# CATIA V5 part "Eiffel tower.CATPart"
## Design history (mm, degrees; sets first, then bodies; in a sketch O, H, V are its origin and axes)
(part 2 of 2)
    symmetry: P8 P14 V, P7 P15 V, L8 L13 V, P11 P16 V, L11 L14 V, P12 P17 V, L12 L15 V, P1 P18 V, L10 L16 V, P4 P19 V, P10 P20 V, L9 L17 V, P6 P21 V, L6 L18 V, P9 P22 V, P5 P23 V, L7 L19 V, P3 P24 V, L2 L20 V, P2 P25 V, L1 L21 V, L4 L22 V, L5 L23 V, L3 L24 V
  Pocket15: profile Sketch37, direction (0, 0.8737, -0.4864), length 0.5
  Sketch38 on face of CloseSurface2, origin (0, -38.813, 21.6056), H (1, 0, 0), V (0, 0.4864, 0.8737)
    line L1 (-40.0899, -6.8005) -> (-28.2213, -6.8005)
    point P1 (-40.0899, -6.8005)
    point P2 (-28.2213, -6.8005)
    reference projected point E1 (-28.2213, -6.8005) from vertex [face of Pocket15 from Sketch37.L7 | face of Pocket8 from Sketch30.L6 | face of CloseSurface2]
    reference projected line E2 (-25.8693, 22.4371) -> (-28.4506, 17.13) from edge [face of CloseSurface2 | face of Pocket12 from Sketch34.L5]
    line L2 (-28.2213, -6.8005) -> (-27.7989, -5.8005)
    reference projected line E4 (-15.8722, 22.4371) -> (-32.8928, -17.8606) from edge [face of CloseSurface2 | face of Pocket8 from Sketch30.L6]
    line L3 (-27.7989, -5.8005) -> (-39.6675, -5.8005)
    point P3 (-27.7989, -5.8005)
    line L4 (-40.0899, -6.8005) -> (-39.6675, -5.8005)
    point P4 (-39.6675, -5.8005)
    point P5 (39.6675, -5.8005)
    point P6 (27.7989, -5.8005)
    line L5 (27.7989, -5.8005) -> (39.6675, -5.8005)
    point P7 (28.2213, -6.8005)
    point P8 (40.0899, -6.8005)
    line L6 (40.0899, -6.8005) -> (28.2213, -6.8005)
    point P9 (27.7989, -5.8005)
    point P10 (28.2213, -6.8005)
    line L7 (28.2213, -6.8005) -> (27.7989, -5.8005)
    point P11 (39.6675, -5.8005)
    point P12 (40.0899, -6.8005)
    line L8 (40.0899, -6.8005) -> (39.6675, -5.8005)
    horizontal: L1 H, L3 H
    coincidence: P2 E1, P1 E2, P5 P11, P6 P9, P7 P10, P8 P12
    parallelism: L2 E4, L4 L2
    symmetry: P4 P5 V, P3 P6 V, L3 L5 V, P2 P7 V, P1 P8 V, L1 L6 V, P3 P9 V, P2 P10 V, L2 L7 V, P4 P11 V, P1 P12 V, L4 L8 V
  Pocket16: profile Sketch38, direction (0, 0.8737, -0.4864), length 0.5
  Sketch39 on face of CloseSurface2, origin (0, -38.813, 21.6056), H (1, 0, 0), V (0, 0.4864, 0.8737)
    line L1 (-39.6035, -5.8005) -> (-31.5781, -1.5166)
    point P1 (-39.6035, -5.8005)
    point P2 (-24.3628, 2.335)
    reference projected line E1 (-35.6047, -11.8753) -> (-28.8395, -8.264) from edge [face of CloseSurface2 | face of Pocket15 from Sketch37.L6]
    reference projected point E2 (-39.6035, -5.8005) from vertex [face of Pocket16 from Sketch38.L3 | face of Pocket12 from Sketch34.L5 | face of CloseSurface2]
    reference projected line E3 (-15.8722, 22.4371) -> (-32.8928, -17.8606) from edge [face of CloseSurface2 | face of Pocket8 from Sketch30.L6]
    line L2 (-38.8589, -4.2694) -> (-32.258, -0.7459)
    point P3 (-38.8589, -4.2694)
    point P4 (-23.7446, 3.7985)
    reference projected line E4 (-25.8693, 22.4371) -> (-28.4506, 17.13) from edge [face of CloseSurface2 | face of Pocket12 from Sketch34.L5]
    reference projected line E6 (-15.8722, 22.4371) -> (-32.8928, -17.8606) from edge [face of CloseSurface2 | face of Pocket8 from Sketch30.L6]
    line L3 (-24.3628, 2.335) -> (-23.7446, 3.7985)
    line L4 (-39.6035, -5.8005) -> (-38.8589, -4.2694)
    point P5 (-34.9348, 3.7985)
    line L5 (-34.9348, 3.7985) -> (-31.3523, -0.2625)
    line L6 (-27.7989, -5.8005) -> (-31.5781, -1.5166)
    point P6 (-27.7989, -5.8005)
    reference projected point E7 (-27.7989, -5.8005) from vertex [face of Pocket16 from Sketch38.L3 | face of Pocket8 from Sketch30.L6 | face of CloseSurface2]
    line L7 (-34.9348, 3.7985) -> (-35.4082, 2.8251)
    point P7 (-35.4082, 2.8251)
    point P8 (-31.5781, -1.5166)
    line L8 (-30.6724, -1.0331) -> (-24.3628, 2.335)
    point P9 (-30.6724, -1.0331)
    point P10 (-32.258, -0.7459)
    line L9 (-31.3523, -0.2625) -> (-23.7446, 3.7985)
    point P11 (-31.3523, -0.2625)
    line L10 (-30.6724, -1.0331) -> (-27.3676, -4.7793)
    line L11 (-32.258, -0.7459) -> (-35.4082, 2.8251)
    line L12 (-27.7989, -5.8005) -> (-27.3676, -4.7793)
    point P12 (-27.3676, -4.7793)
    point P13 (31.5781, -1.5166)
    point P14 (39.6035, -5.8005)
    line L13 (39.6035, -5.8005) -> (31.5781, -1.5166)
    point P15 (32.258, -0.7459)
    point P16 (38.8589, -4.2694)
    line L14 (38.8589, -4.2694) -> (32.258, -0.7459)
    point P17 (35.4082, 2.8251)
    line L15 (32.258, -0.7459) -> (35.4082, 2.8251)
    point P18 (31.3523, -0.2625)
    point P19 (34.9348, 3.7985)
    line L16 (34.9348, 3.7985) -> (31.3523, -0.2625)
    point P20 (23.7446, 3.7985)
    line L17 (31.3523, -0.2625) -> (23.7446, 3.7985)
    point P21 (24.3628, 2.335)
    point P22 (30.6724, -1.0331)
    line L18 (30.6724, -1.0331) -> (24.3628, 2.335)
    point P23 (27.3676, -4.7793)
    line L19 (30.6724, -1.0331) -> (27.3676, -4.7793)
    point P24 (27.7989, -5.8005)
    line L20 (27.7989, -5.8005) -> (31.5781, -1.5166)
    line L21 (34.9348, 3.7985) -> (35.4082, 2.8251)
    line L22 (24.3628, 2.335) -> (23.7446, 3.7985)
    line L23 (27.7989, -5.8005) -> (27.3676, -4.7793)
    line L24 (39.6035, -5.8005) -> (38.8589, -4.2694)
    parallelism: L1 E1, L6 L5, L7 L4, L12 L3
    coincidence: P1 E2, P2 E3, P3 E4, P4 E6, P5 L4, P6 E7, L5 P9, L1 L8, L6 P10, L2 L9, L5 L10, L6 L11
    fix: L5
    symmetry: P8 P13 V, P1 P14 V, L1 L13 V, P10 P15 V, P3 P16 V, L2 L14 V, P7 P17 V, L11 L15 V, P11 P18 V, P5 P19 V, L5 L16 V, P4 P20 V, L9 L17 V, P2 P21 V, P9 P22 V, L8 L18 V, P12 P23 V, L10 L19 V, P6 P24 V, L6 L20 V, L7 L21 V, L3 L22 V, L12 L23 V, L4 L24 V
  Pocket17: profile Sketch39, direction (0, 0.8737, -0.4864), length 0.5
  Sketch40 on face of CloseSurface2, origin (0, -38.813, 21.6056), H (1, 0, 0), V (0, 0.4864, 0.8737)
    line L1 (-34.9348, 3.7985) -> (-23.7446, 3.7985)
    point P1 (-34.9348, 3.7985)
    point P2 (-23.7446, 3.7985)
    reference projected point E1 (-34.9348, 3.7985) from vertex [face of Pocket17 from Sketch39.L5 | face of Pocket12 from Sketch34.L5 | face of CloseSurface2]
    reference projected line E2 (-15.8722, 22.4371) -> (-32.8928, -17.8606) from edge [face of CloseSurface2 | face of Pocket8 from Sketch30.L6]
    line L2 (-34.4484, 4.7985) -> (-23.3222, 4.7985)
    point P3 (-23.3222, 4.7985)
    point P4 (-34.4484, 4.7985)
    line L3 (-23.3222, 4.7985) -> (-26.878, 8.8292)
    reference projected line E3 (-31.3523, -0.2625) -> (-34.9348, 3.7985) from edge [face of CloseSurface2 | face of Pocket17 from Sketch39.L5]
    point P5 (-30.4942, 12.9283)
    line L4 (-22.8905, 5.8207) -> (-25.9707, 9.3123)
    point P6 (-22.8905, 5.8207)
    point P7 (-30.0203, 13.9027)
    point P8 (-19.4769, 13.9027)
    line L5 (-19.4769, 13.9027) -> (-26.6507, 10.0831)
    point P9 (-33.7048, 6.3273)
    line L6 (-20.0942, 12.4411) -> (-25.9707, 9.3123)
    point P10 (-20.0942, 12.4411)
    point P11 (-25.9707, 9.3123)
    line L7 (-26.6507, 10.0831) -> (-30.0203, 13.9027)
    point P12 (-26.6507, 10.0831)
    point P13 (-26.878, 8.8292)
    line L8 (-27.5581, 9.6) -> (-30.4942, 12.9283)
    point P14 (-27.5581, 9.6)
    line L9 (-26.878, 8.8292) -> (-34.4484, 4.7985)
    line L10 (-27.5581, 9.6) -> (-33.7048, 6.3273)
    line L11 (-20.0942, 12.4411) -> (-19.4769, 13.9027)
    line L12 (-30.4942, 12.9283) -> (-30.0203, 13.9027)
    line L13 (-23.7446, 3.7985) -> (-23.3222, 3.7985)
    point P15 (-23.3222, 3.7985)
    line L14 (-23.3222, 3.7985) -> (-22.6049, 5.4969)
    point P16 (-22.6049, 5.4969)
    line L15 (-22.6049, 5.4969) -> (-22.8905, 5.8207)
    line L16 (-34.9348, 3.7985) -> (-35.3834, 3.7985)
    point P17 (-35.3834, 3.7985)
    line L17 (-35.3834, 3.7985) -> (-34.3102, 6.005)
    point P18 (-34.3102, 6.005)
    line L18 (-34.3102, 6.005) -> (-33.7048, 6.3273)
    construction line L19 through (0, 7.597) direction (0, -1)
    point P21 (23.3222, 4.7985)
    point P22 (34.4484, 4.7985)
    line L20 (34.4484, 4.7985) -> (23.3222, 4.7985)
    point P23 (26.878, 8.8292)
    line L21 (26.878, 8.8292) -> (34.4484, 4.7985)
    point P24 (33.7048, 6.3273)
    point P25 (27.5581, 9.6)
    line L22 (27.5581, 9.6) -> (33.7048, 6.3273)
    point P26 (30.4942, 12.9283)
    line L23 (27.5581, 9.6) -> (30.4942, 12.9283)
    point P27 (30.0203, 13.9027)
    point P28 (26.6507, 10.0831)
    line L24 (26.6507, 10.0831) -> (30.0203, 13.9027)
    point P29 (19.4769, 13.9027)
    line L25 (19.4769, 13.9027) -> (26.6507, 10.0831)
    point P30 (25.9707, 9.3123)
    point P31 (20.0942, 12.4411)
    line L26 (20.0942, 12.4411) -> (25.9707, 9.3123)
    point P32 (22.8905, 5.8207)
    line L27 (22.8905, 5.8207) -> (25.9707, 9.3123)
    line L28 (23.3222, 4.7985) -> (26.878, 8.8292)
    point P33 (22.6049, 5.4969)
    point P34 (23.3222, 3.7985)
    line L29 (23.3222, 3.7985) -> (22.6049, 5.4969)
    line L30 (22.6049, 5.4969) -> (22.8905, 5.8207)
    point P35 (23.7446, 3.7985)
    point P36 (34.9348, 3.7985)
    line L31 (34.9348, 3.7985) -> (23.7446, 3.7985)
    line L32 (23.7446, 3.7985) -> (23.3222, 3.7985)
    point P37 (35.3834, 3.7985)
    line L33 (34.9348, 3.7985) -> (35.3834, 3.7985)
    point P38 (34.3102, 6.005)
    line L34 (35.3834, 3.7985) -> (34.3102, 6.005)
    line L35 (34.3102, 6.005) -> (33.7048, 6.3273)
    line L36 (30.4942, 12.9283) -> (30.0203, 13.9027)
    line L37 (20.0942, 12.4411) -> (19.4769, 13.9027)
    distance L3 L4 = 1
    distance L6 L5 = 1
    horizontal: L1 H, L2 H, L13 H, L16 H
    coincidence: P1 E1, P2 E2, L4 L7, L6 P13, L5 P14, L3 L8, L6 L9, L5 L10, P16 L4, P18 L5
    parallelism: L3 E3, L15 L3, L17 L12, L18 L5
    symmetry: V L19 L1, P3 P21 L19, P4 P22 L19, L2 L20 L19, P13 P23 L19, L9 L21 L19, P9 P24 L19, P14 P25 L19, L10 L22 L19, P5 P26 L19, L8 L23 L19, P7 P27 L19, P12 P28 L19, L7 L24 L19, P8 P29 L19, L5 L25 L19, P11 P30 L19, P10 P31 L19, L6 L26 L19, P6 P32 L19, L4 L27 L19, L3 L28 L19, P16 P33 L19, P15 P34 L19, L14 L29 L19, L15 L30 L19, P2 P35 L19, P1 P36 L19, L1 L31 L19, L13 L32 L19, P17 P37 L19, L16 L33 L19, P18 P38 L19, L17 L34 L19, L18 L35 L19, L12 L36 L19, L11 L37 L19
  Pocket18: profile Sketch40, direction (0, 0.8737, -0.4864), length 0.5
  Sketch41 on face of CloseSurface2, origin (0, -38.813, 21.6056), H (1, 0, 0), V (0, 0.4864, 0.8737)
    line L1 (-30.0203, 13.9027) -> (-19.4769, 13.9027)
    point P1 (-30.0203, 13.9027)
    point P2 (-19.4769, 13.9027)
    reference projected line E1 (-25.8693, 22.4371) -> (-28.4506, 17.13) from edge [face of CloseSurface2 | face of Pocket12 from Sketch34.L5]
    reference projected point E3 (-30.0203, 13.9027) from vertex [face of Pocket18 from Sketch40.L7 | face of Pocket12 from Sketch34.L5 | face of CloseSurface2]
    reference projected line E4 (-15.8722, 22.4371) -> (-32.8928, -17.8606) from edge [face of CloseSurface2 | face of Pocket8 from Sketch30.L6]
    line L2 (-29.5339, 14.9027) -> (-19.0545, 14.9027)
    point P3 (-29.5339, 14.9027)
    reference projected line E5 (-25.8693, 22.4371) -> (-28.4506, 17.13) from edge [face of CloseSurface2 | face of Pocket12 from Sketch34.L5]
    line L3 (-30.0203, 13.9027) -> (-29.5339, 14.9027)
    line L4 (-19.4769, 13.9027) -> (-19.0545, 14.9027)
    reference projected line E7 (-15.8722, 22.4371) -> (-32.8928, -17.8606) from edge [face of CloseSurface2 | face of Pocket8 from Sketch30.L6]
    point P4 (-19.0545, 14.9027)
    point P5 (29.5339, 14.9027)
    point P6 (30.0203, 13.9027)
    line L5 (30.0203, 13.9027) -> (29.5339, 14.9027)
    point P7 (19.0545, 14.9027)
    line L6 (29.5339, 14.9027) -> (19.0545, 14.9027)
    point P8 (19.4769, 13.9027)
    line L7 (30.0203, 13.9027) -> (19.4769, 13.9027)
    line L8 (19.4769, 13.9027) -> (19.0545, 14.9027)
    distance L1 L2 = 1
    horizontal: L1 H, L2 H
    coincidence: P1 E1, P1 E3, P2 E4, P3 E5
    parallelism: L4 E7
    symmetry: P3 P5 V, P1 P6 V, L3 L5 V, P4 P7 V, L2 L6 V, P2 P8 V, L1 L7 V, L4 L8 V
  Pocket19: profile Sketch41, direction (0, 0.8737, -0.4864), length 0.5
  CircPattern17: of Pocket19, instances 4, angular step 90, axis from edge [ZX plane of AxisSystem1 | YZ plane of AxisSystem1]
  CircPattern18: of Pocket18, instances 4, angular step 90, axis from edge [ZX plane of AxisSystem1 | YZ plane of AxisSystem1]
  CircPattern19: of Pocket16, instances 4, angular step 90, axis from edge [ZX plane of AxisSystem1 | YZ plane of AxisSystem1]
  CircPattern20: of Pocket17, instances 4, angular step 90, axis from edge [ZX plane of AxisSystem1 | YZ plane of AxisSystem1]
  CircPattern21: of Pocket15, instances 4, angular step 90, axis from edge [ZX plane of AxisSystem1 | YZ plane of AxisSystem1]
  Sketch42 on face of CloseSurface2, origin (0, -38.813, 21.6056), H (1, 0, 0), V (0, 0.4864, 0.8737)
    arc A1 centre (0, -15.7693) radius 30 from (17.6145, 8.5151) to (16.7953, 9.0886) ccw
    reference projected arc E1 centre (0, -15.7693) radius 30 from (22.7492, 3.7877) to (-22.7492, 3.7877) ccw from edge [face of CloseSurface2 | face of Pocket9 from Sketch31.A1]
    line L1 (17.6145, 8.5151) -> (19.9099, 11.7932)
    line L2 (-17.6145, 8.5151) -> (-19.9969, 11.9175)
    line L3 (-19.9969, 11.9175) -> (-19.5008, 12.9525)
    line L4 (-17.6271, 16.3175) -> (-16.7442, 16.787)
    line L5 (-12.9374, 16.5386) -> (-11.8663, 16.5386)
    line L6 (16.7034, 16.7103) -> (17.7666, 16.5797)
    line L7 (19.4776, 12.9193) -> (19.9099, 11.7932)
    point P7 (12.9374, 16.5386)
    point P8 (11.8663, 16.5386)
    point P9 (8.5706, 16.5386)
    point P10 (7.54, 16.5386)
    point P11 (4.4707, 16.5386)
    point P12 (3.4632, 16.5386)
    point P13 (0.5, 16.5386)
    point P14 (-0.5, 16.5386)
    point P15 (-3.4632, 16.5386)
    point P16 (-4.4707, 16.5386)
    point P17 (-7.54, 16.5386)
    point P18 (-8.5706, 16.5386)
    line L8 (-16.7953, 9.0886) -> (-19.5008, 12.9525)
    point P25 (-16.7953, 9.0886)
    line L9 (-13.6407, 10.9502) -> (-16.7442, 16.787)
    point P26 (-13.6407, 10.9502)
    line L10 (-14.5237, 10.4807) -> (-17.6271, 16.3175)
    point P27 (-14.5237, 10.4807)
    line L11 (-11.2163, 12.055) -> (-12.9374, 16.5386)
    point P28 (-11.2163, 12.055)
    line L12 (-7.7418, 13.2146) -> (-8.5706, 16.5386)
    point P29 (-7.7418, 13.2146)
    line L13 (-10.2828, 12.4134) -> (-11.8663, 16.5386)
    point P30 (-10.2828, 12.4134)
    line L14 (-6.7715, 13.4565) -> (-7.54, 16.5386)
    point P31 (-6.7715, 13.4565)
    line L15 (-4.1518, 13.942) -> (-4.4707, 16.5386)
    point P32 (-4.1518, 13.942)
    line L16 (-3.1593, 14.0639) -> (-3.4632, 16.5386)
    point P33 (-3.1593, 14.0639)
    line L17 (-0.5, 14.2265) -> (-0.5, 16.5386)
    point P34 (-0.5, 14.2265)
    line L18 (0.5, 14.2265) -> (0.5, 16.5386)
    point P35 (0.5, 14.2265)
    line L19 (3.1593, 14.0639) -> (3.4632, 16.5386)
    point P36 (3.1593, 14.0639)
    line L20 (4.1518, 13.942) -> (4.4707, 16.5386)
    point P37 (4.1518, 13.942)
    line L21 (6.7715, 13.4565) -> (7.54, 16.5386)
    point P38 (6.7715, 13.4565)
    line L22 (10.2828, 12.4134) -> (11.8663, 16.5386)
    point P39 (10.2828, 12.4134)
    line L23 (7.7418, 13.2146) -> (8.5706, 16.5386)
    point P40 (7.7418, 13.2146)
    line L24 (11.2163, 12.055) -> (12.9374, 16.5386)
    point P41 (11.2163, 12.055)
    line L25 (13.6407, 10.9502) -> (16.7034, 16.7103)
    point P42 (13.6407, 10.9502)
    line L26 (14.5237, 10.4807) -> (17.7666, 16.5797)
    point P43 (14.5237, 10.4807)
    line L27 (16.7953, 9.0886) -> (19.4776, 12.9193)
    line L28 (-8.5706, 16.5386) -> (-7.54, 16.5386)
    line L29 (-4.4707, 16.5386) -> (-3.4632, 16.5386)
    line L30 (-0.5, 16.5386) -> (0.5, 16.5386)
    line L31 (3.4632, 16.5386) -> (4.4707, 16.5386)
    line L32 (7.54, 16.5386) -> (8.5706, 16.5386)
    line L33 (11.8663, 16.5386) -> (12.9374, 16.5386)
    arc A2 centre (0, -15.7693) radius 30 from (14.5237, 10.4807) to (13.6407, 10.9502) ccw
    arc A3 centre (0, -15.7693) radius 30 from (11.2163, 12.055) to (10.2828, 12.4134) ccw
    arc A4 centre (0, -15.7693) radius 30 from (7.7418, 13.2146) to (6.7715, 13.4565) ccw
    arc A5 centre (0, -15.7693) radius 30 from (4.1518, 13.942) to (3.1593, 14.0639) ccw
    arc A6 centre (0, -15.7693) radius 30 from (0.5, 14.2265) to (-0.5, 14.2265) ccw
    arc A7 centre (0, -15.7693) radius 30 from (-3.1593, 14.0639) to (-4.1518, 13.942) ccw
    arc A8 centre (0, -15.7693) radius 30 from (-6.7715, 13.4565) to (-7.7418, 13.2146) ccw
    arc A9 centre (0, -15.7693) radius 30 from (-10.2828, 12.4134) to (-11.2163, 12.055) ccw
    arc A10 centre (0, -15.7693) radius 30 from (-13.6407, 10.9502) to (-14.5237, 10.4807) ccw
    arc A11 centre (0, -15.7693) radius 30 from (-16.7953, 9.0886) to (-17.6145, 8.5151) ccw
    concentricity: A1 E1
    tangency: L3 A1
    horizontal: L5 H, L28 H, L29 H, L30 H, L31 H, L32 H, L33 H
    coincidence: L5 P7, L5 P8, L5 P9, L5 P10, L5 P11, L5 P12, L5 P13, L5 P14, L5 P15, L5 P16, L5 P17, L5 P18, A1 P25, A1 P26, A1 P27, A1 P28, A1 P29, A1 P30, A1 P31, A1 P32, A1 P33, A1 P34, A1 P35, A1 P36, A1 P37, A1 P38, A1 P39, A1 P40, A1 P41, A1 P42, A1 P43, L5 L28, L28 L29, L29 L30, L30 L31, L31 L32, L32 L33, A1 A2, A2 A3, A3 A4, A4 A5, A5 A6, A6 A7, A7 A8, A8 A9, A9 A10, A10 A11
  Pocket20: profile Sketch42, direction (0, 0.8737, -0.4864), length 0.5
  CircPattern22: of Pocket20, instances 4, angular step 90, axis from edge [ZX plane of AxisSystem1 | YZ plane of AxisSystem1]
  Sketch43 on face of CloseSurface4, origin (0, -33.1899, 7.6699), H (1, 0, 0), V (0, 0.2252, 0.9743)
    line L1 (-20.053, 49.5728) -> (-16.9434, 51.7501)
    point P1 (-20.053, 49.5728)
    point P2 (-14.1177, 53.7287)
    line L2 (-19.7267, 51.0221) -> (-17.6463, 52.4788)
    point P3 (-19.7267, 51.0221)
    point P4 (-13.875, 55.1195)
    line L3 (-14.8432, 49.5728) -> (-16.9434, 51.7501)
    point P5 (-14.8432, 49.5728)
    point P6 (-19.0671, 53.9517)
    point P7 (-19.239, 52.9666)
    reference projected line E1 (-20.225, 48.5877) -> (-11.975, 85.2285) from edge [face of CloseSurface4 | face of Pocket13 from Sketch35.L11]
    point P8 (-18.9761, 54.1344)
    line L4 (-18.8041, 55.1195) -> (-16.817, 53.0594)
    point P9 (-18.8041, 55.1195)
    point P10 (-14.6303, 50.7925)
    reference projected line E2 (-20.225, 48.5877) -> (-11.975, 85.2285) from edge [face of CloseSurface4 | face of Pocket13 from Sketch35.L11]
    line L5 (-14.8432, 49.5728) -> (-14.6303, 50.7925)
    line L6 (-20.053, 49.5728) -> (-19.7267, 51.0221)
    line L7 (-14.1177, 53.7287) -> (-13.875, 55.1195)
    line L8 (-19.0671, 53.9517) -> (-18.8041, 55.1195)
    point P11 (-16.9434, 51.7501)
    line L9 (-16.1142, 52.3308) -> (-14.1177, 53.7287)
    point P12 (-16.1142, 52.3308)
    point P13 (-16.817, 53.0594)
    line L10 (-16.1142, 52.3308) -> (-14.6303, 50.7925)
    point P14 (-17.6463, 52.4788)
    line L11 (-16.817, 53.0594) -> (-13.875, 55.1195)
    line L12 (-17.6463, 52.4788) -> (-19.0671, 53.9517)
    point P15 (19.7267, 51.0221)
    point P16 (20.053, 49.5728)
    line L13 (20.053, 49.5728) -> (19.7267, 51.0221)
    point P17 (16.9434, 51.7501)
    line L14 (20.053, 49.5728) -> (16.9434, 51.7501)
    point P18 (14.8432, 49.5728)
    line L15 (14.8432, 49.5728) -> (16.9434, 51.7501)
    point P19 (14.6303, 50.7925)
    line L16 (14.8432, 49.5728) -> (14.6303, 50.7925)
    point P20 (16.1142, 52.3308)
    line L17 (16.1142, 52.3308) -> (14.6303, 50.7925)
    point P21 (14.1177, 53.7287)
    line L18 (16.1142, 52.3308) -> (14.1177, 53.7287)
    point P22 (13.875, 55.1195)
    line L19 (14.1177, 53.7287) -> (13.875, 55.1195)
    point P23 (16.817, 53.0594)
    line L20 (16.817, 53.0594) -> (13.875, 55.1195)
    point P24 (18.8041, 55.1195)
    line L21 (18.8041, 55.1195) -> (16.817, 53.0594)
    point P25 (19.0671, 53.9517)
    line L22 (19.0671, 53.9517) -> (18.8041, 55.1195)
    point P26 (17.6463, 52.4788)
    line L23 (17.6463, 52.4788) -> (19.0671, 53.9517)
    line L24 (19.7267, 51.0221) -> (17.6463, 52.4788)
    distance L2 L1 = 1
    distance L4 L3 = 1
    coincidence: P7 E1, P8 E2, L4 P12, L1 L9, L2 P13, L4 L10, L3 P14, L2 L11, L3 L12
    parallelism: L7 L5, L8 L6
    symmetry: P3 P15 V, P1 P16 V, L6 L13 V, P11 P17 V, L1 L14 V, P5 P18 V, L3 L15 V, P10 P19 V, L5 L16 V, P12 P20 V, L10 L17 V, P2 P21 V, L9 L18 V, P4 P22 V, L7 L19 V, P13 P23 V, L11 L20 V, P9 P24 V, L4 L21 V, P6 P25 V, L8 L22 V, P14 P26 V, L12 L23 V, L2 L24 V
  Pocket21: profile Sketch43, direction (0, 0.9743, -0.2252), length 0.5
  Sketch44 on face of CloseSurface4, origin (0, -33.1899, 7.6699), H (1, 0, 0), V (0, 0.2252, 0.9743)
    line L1 (-18.7637, 55.0776) -> (-13.9348, 55.0776)
    point P1 (-18.7637, 55.0776)
    point P2 (-13.9348, 55.0776)
    reference projected point E1 (-18.7637, 55.0776) from vertex [face of Pocket21 from Sketch43.L4 | face of Pocket13 from Sketch35.L11 | face of CloseSurface4]
    reference projected line E2 (-13.875, 55.1195) -> (-16.817, 53.0594) from edge [face of CloseSurface4 | face of Pocket21 from Sketch43.L11]
    line L2 (-18.5386, 56.0776) -> (-13.7077, 56.0776)
    point P3 (-18.5386, 56.0776)
    point P4 (-13.7077, 56.0776)
    reference projected line E3 (-20.225, 48.5877) -> (-11.975, 85.2285) from edge [face of CloseSurface4 | face of Pocket13 from Sketch35.L11]
    reference projected line E4 (-8.6194, 85.2285) -> (-15.0151, 48.5877) from edge [face of CloseSurface4 | face of Pocket13 from Sketch35.L10]
    line L3 (-13.7077, 56.0776) -> (-13.8652, 55.0776)
    point P5 (-13.8652, 55.0776)
    line L4 (-13.8652, 55.0776) -> (-13.9348, 55.0776)
    line L5 (-18.5386, 56.0776) -> (-18.7637, 55.0776)
    point P6 (13.9348, 55.0776)
    point P7 (18.7637, 55.0776)
    line L6 (18.7637, 55.0776) -> (13.9348, 55.0776)
    point P8 (18.5386, 56.0776)
    line L7 (18.5386, 56.0776) -> (18.7637, 55.0776)
    point P9 (13.7077, 56.0776)
    line L8 (18.5386, 56.0776) -> (13.7077, 56.0776)
    point P10 (13.8652, 55.0776)
    line L9 (13.7077, 56.0776) -> (13.8652, 55.0776)
    line L10 (13.8652, 55.0776) -> (13.9348, 55.0776)
    distance L2 L1 = 1
    horizontal: L1 H, L2 H, L4 H
    coincidence: P1 E1, P2 E2, P3 E3, P4 E4, P5 L1
    symmetry: P2 P6 V, P1 P7 V, L1 L6 V, P3 P8 V, L5 L7 V, P4 P9 V, L2 L8 V, P5 P10 V, L3 L9 V, L4 L10 V
  Pocket22: profile Sketch44, direction (0, 0.9743, -0.2252), length 0.5
  CircPattern23: of Pocket21, instances 4, angular step 90, axis from edge [ZX plane of AxisSystem1 | YZ plane of AxisSystem1]
  CircPattern24: of Pocket22, instances 4, angular step 90, axis from edge [ZX plane of AxisSystem1 | YZ plane of AxisSystem1]
  Sketch45 on face of CloseSurface4, origin (0, -33.1899, 7.6699), H (1, 0, 0), V (0, 0.2252, 0.9743)
    line L1 (-18.5386, 56.0776) -> (-15.6552, 58.0965)
    point P1 (-18.5386, 56.0776)
    point P2 (-13.0351, 59.9311)
    reference projected line E1 (-13.875, 55.1195) -> (-16.817, 53.0594) from edge [face of CloseSurface4 | face of Pocket21 from Sketch43.L11]
    reference projected point E2 (-18.5386, 56.0776) from vertex [face of Pocket22 from Sketch44.L2 | face of Pocket13 from Sketch35.L11 | face of CloseSurface4]
    reference projected line E3 (-8.6194, 85.2285) -> (-15.0151, 48.5877) from edge [face of CloseSurface4 | face of Pocket13 from Sketch35.L10]
    line L2 (-18.2122, 57.5268) -> (-16.3581, 58.8251)
    point P3 (-18.2122, 57.5268)
    point P4 (-12.7923, 61.3219)
    reference projected line E4 (-20.225, 48.5877) -> (-11.975, 85.2285) from edge [face of CloseSurface4 | face of Pocket13 from Sketch35.L11]
    reference projected line E5 (-8.6194, 85.2285) -> (-15.0151, 48.5877) from edge [face of CloseSurface4 | face of Pocket13 from Sketch35.L10]
    line L3 (-13.7077, 56.0776) -> (-15.6552, 58.0965)
    point P5 (-13.7077, 56.0776)
    point P6 (-17.6243, 60.1379)
    reference projected line E6 (-16.817, 53.0594) -> (-18.7637, 55.0776) from edge [face of CloseSurface4 | face of Pocket21 from Sketch43.L4]
    reference projected point E7 (-13.7077, 56.0776) from vertex [face of Pocket22 from Sketch44.L2 | face of Pocket13 from Sketch35.L10 | face of CloseSurface4]
    reference projected line E8 (-20.225, 48.5877) -> (-11.975, 85.2285) from edge [face of CloseSurface4 | face of Pocket13 from Sketch35.L11]
    line L4 (-17.3566, 61.3269) -> (-15.5137, 59.4164)
    point P7 (-17.3566, 61.3269)
    point P8 (-13.491, 57.3194)
    point P9 (-17.3566, 61.3269)
    reference projected line E9 (-20.225, 48.5877) -> (-11.975, 85.2285) from edge [face of CloseSurface4 | face of Pocket13 from Sketch35.L11]
    reference projected line E10 (-8.6194, 85.2285) -> (-15.0151, 48.5877) from edge [face of CloseSurface4 | face of Pocket13 from Sketch35.L10]
    line L5 (-13.7077, 56.0776) -> (-13.491, 57.3194)
    line L6 (-13.0351, 59.9311) -> (-12.7923, 61.3219)
    line L7 (-17.3566, 61.3269) -> (-17.6243, 60.1379)
    line L8 (-18.2122, 57.5268) -> (-18.5386, 56.0776)
    point P10 (-15.5137, 59.4164)
    line L9 (-14.8109, 58.6877) -> (-13.491, 57.3194)
    point P11 (-14.8109, 58.6877)
    point P12 (-16.3581, 58.8251)
    line L10 (-15.5137, 59.4164) -> (-12.7923, 61.3219)
    point P13 (-15.6552, 58.0965)
    line L11 (-16.3581, 58.8251) -> (-17.6243, 60.1379)
    line L12 (-14.8109, 58.6877) -> (-13.0351, 59.9311)
    reference intersected line E11 through (0, 0) direction (0, 1) from yz-plane
    point P16 (15.6552, 58.0965)
    point P17 (18.5386, 56.0776)
    line L13 (18.5386, 56.0776) -> (15.6552, 58.0965)
    point P18 (18.2122, 57.5268)
    line L14 (18.2122, 57.5268) -> (18.5386, 56.0776)
    point P19 (16.3581, 58.8251)
    line L15 (18.2122, 57.5268) -> (16.3581, 58.8251)
    point P20 (17.6243, 60.1379)
    line L16 (16.3581, 58.8251) -> (17.6243, 60.1379)
    point P21 (17.3566, 61.3269)
    line L17 (17.3566, 61.3269) -> (17.6243, 60.1379)
    point P22 (15.5137, 59.4164)
    line L18 (17.3566, 61.3269) -> (15.5137, 59.4164)
    point P23 (12.7923, 61.3219)
    line L19 (15.5137, 59.4164) -> (12.7923, 61.3219)
    point P24 (13.0351, 59.9311)
    line L20 (13.0351, 59.9311) -> (12.7923, 61.3219)
    point P25 (14.8109, 58.6877)
    line L21 (14.8109, 58.6877) -> (13.0351, 59.9311)
    point P26 (13.491, 57.3194)
    line L22 (14.8109, 58.6877) -> (13.491, 57.3194)
    point P27 (13.7077, 56.0776)
    line L23 (13.7077, 56.0776) -> (13.491, 57.3194)
    line L24 (13.7077, 56.0776) -> (15.6552, 58.0965)
    distance L1 L2 = 1
    parallelism: L1 E1, L3 E6, L4 L3, L6 L5, L8 L7
    coincidence: P1 E2, P2 E3, P3 E4, P4 E5, P5 E7, P6 E8, P9 E9, P7 P9, P8 E10, L2 P10, L1 P11, L4 L9, L3 P12, L2 L10, L3 L11, L1 L12
    symmetry: P13 P16 E11, P1 P17 E11, L1 L13 E11, P3 P18 E11, L8 L14 E11, P12 P19 E11, L2 L15 E11, P6 P20 E11, L11 L16 E11, P7 P21 E11, L7 L17 E11, P10 P22 E11, L4 L18 E11, P4 P23 E11, L10 L19 E11, P2 P24 E11, L6 L20 E11, P11 P25 E11, L12 L21 E11, P8 P26 E11, L9 L22 E11, P5 P27 E11, L5 L23 E11, L3 L24 E11
  Pocket23: profile Sketch45, direction (0, 0.9743, -0.2252), length 0.5
  Sketch46 on face of CloseSurface4, origin (0, -33.1899, 7.6699), H (1, 0, 0), V (0, 0.2252, 0.9743)
    line L1 (-17.3566, 61.3269) -> (-12.7915, 61.3269)
    point P1 (-17.3566, 61.3269)
    point P2 (-12.7915, 61.3269)
    reference projected point E1 (-17.3566, 61.3269) from vertex [face of Pocket23 from Sketch45.L4 | face of Pocket13 from Sketch35.L11 | face of CloseSurface4]
    reference projected line E2 (-8.6194, 85.2285) -> (-15.0151, 48.5877) from edge [face of CloseSurface4 | face of Pocket13 from Sketch35.L10]
    line L2 (-17.3566, 62.3269) -> (-12.4148, 62.3269)
    point P3 (-17.3566, 62.3269)
    point P4 (-12.4148, 62.3269)
    line L3 (-12.7915, 61.3269) -> (-12.4148, 62.3269)
    line L4 (-17.3566, 61.3269) -> (-17.3566, 62.3269)
    point P5 (17.3566, 62.3269)
    point P6 (17.3566, 61.3269)
    line L5 (17.3566, 61.3269) -> (17.3566, 62.3269)
    point P7 (12.4148, 62.3269)
    line L6 (17.3566, 62.3269) -> (12.4148, 62.3269)
    point P8 (12.7915, 61.3269)
    line L7 (17.3566, 61.3269) -> (12.7915, 61.3269)
    line L8 (12.7915, 61.3269) -> (12.4148, 62.3269)
    distance L2 L1 = 1
    horizontal: L1 H, L2 H
    coincidence: P1 E1, P2 E2
    vertical: L4 V
    symmetry: P3 P5 V, P1 P6 V, L4 L5 V, P4 P7 V, L2 L6 V, P2 P8 V, L1 L7 V, L3 L8 V
  Pocket24: profile Sketch46, direction (0, 0.9743, -0.2252), length 0.5
  CircPattern25: of Pocket23, instances 4, angular step 90, axis from edge [ZX plane of AxisSystem1 | YZ plane of AxisSystem1]
  CircPattern26: of Pocket24, instances 4, angular step 90, axis from edge [ZX plane of AxisSystem1 | YZ plane of AxisSystem1]
  Sketch47 on face of CloseSurface4, origin (0, -33.1899, 7.6699), H (1, 0, 0), V (0, 0.2252, 0.9743)
    line L1 (-17.1315, 62.3269) -> (-14.4369, 64.2136)
    point P1 (-17.1315, 62.3269)
    point P2 (-11.9883, 65.9282)
    reference projected line E1 (-12.7923, 61.3219) -> (-15.5137, 59.4164) from edge [face of CloseSurface4 | face of Pocket23 from Sketch45.L10]
    reference projected point E2 (-17.1315, 62.3269) from vertex [face of Pocket24 from Sketch46.L2 | face of Pocket13 from Sketch35.L11 | face of CloseSurface4]
    reference projected line E3 (-8.6194, 85.2285) -> (-15.0151, 48.5877) from edge [face of CloseSurface4 | face of Pocket13 from Sketch35.L10]
    line L2 (-16.8052, 63.7761) -> (-15.1397, 64.9423)
    point P3 (-16.8052, 63.7761)
    point P4 (-11.7455, 67.3189)
    reference projected line E4 (-20.225, 48.5877) -> (-11.975, 85.2285) from edge [face of CloseSurface4 | face of Pocket13 from Sketch35.L11]
    reference projected line E5 (-8.6194, 85.2285) -> (-15.0151, 48.5877) from edge [face of CloseSurface4 | face of Pocket13 from Sketch35.L10]
    line L3 (-12.6169, 62.3269) -> (-14.4369, 64.2136)
    point P5 (-12.6169, 62.3269)
    point P6 (-16.2771, 66.1214)
    reference projected line E6 (-15.5137, 59.4164) -> (-17.3566, 61.3269) from edge [face of CloseSurface4 | face of Pocket23 from Sketch45.L4]
    reference projected point E7 (-12.6169, 62.3269) from vertex [face of Pocket24 from Sketch46.L2 | face of Pocket13 from Sketch35.L10 | face of CloseSurface4]
    reference projected line E8 (-20.225, 48.5877) -> (-11.975, 85.2285) from edge [face of CloseSurface4 | face of Pocket13 from Sketch35.L11]
    line L4 (-12.404, 63.5466) -> (-13.6076, 64.7943)
    point P7 (-12.404, 63.5466)
    point P8 (-16.0142, 67.2892)
    reference projected line E9 (-8.6194, 85.2285) -> (-15.0151, 48.5877) from edge [face of CloseSurface4 | face of Pocket13 from Sketch35.L10]
    reference projected line E10 (-20.225, 48.5877) -> (-11.975, 85.2285) from edge [face of CloseSurface4 | face of Pocket13 from Sketch35.L11]
    line L5 (-12.6169, 62.3269) -> (-12.404, 63.5466)
    line L6 (-11.9883, 65.9282) -> (-11.7455, 67.3189)
    line L7 (-16.0142, 67.2892) -> (-16.2771, 66.1214)
    line L8 (-17.1315, 62.3269) -> (-16.8052, 63.7761)
    point P9 (-13.6076, 64.7943)
    line L9 (-14.3104, 65.523) -> (-16.0142, 67.2892)
    point P10 (-14.3104, 65.523)
    point P11 (-15.1397, 64.9423)
    line L10 (-14.3104, 65.523) -> (-11.7455, 67.3189)
    point P12 (-14.4369, 64.2136)
    line L11 (-15.1397, 64.9423) -> (-16.2771, 66.1214)
    line L12 (-13.6076, 64.7943) -> (-11.9883, 65.9282)
    point P13 (16.8052, 63.7761)
    point P14 (17.1315, 62.3269)
    line L13 (17.1315, 62.3269) -> (16.8052, 63.7761)
    point P15 (14.4369, 64.2136)
    line L14 (17.1315, 62.3269) -> (14.4369, 64.2136)
    point P16 (12.6169, 62.3269)
    line L15 (12.6169, 62.3269) -> (14.4369, 64.2136)
    point P17 (12.404, 63.5466)
    line L16 (12.6169, 62.3269) -> (12.404, 63.5466)
    point P18 (13.6076, 64.7943)
    line L17 (12.404, 63.5466) -> (13.6076, 64.7943)
    point P19 (11.9883, 65.9282)
    line L18 (13.6076, 64.7943) -> (11.9883, 65.9282)
    point P20 (11.7455, 67.3189)
    line L19 (11.9883, 65.9282) -> (11.7455, 67.3189)
    point P21 (14.3104, 65.523)
    line L20 (14.3104, 65.523) -> (11.7455, 67.3189)
    point P22 (16.0142, 67.2892)
    line L21 (14.3104, 65.523) -> (16.0142, 67.2892)
    point P23 (16.2771, 66.1214)
    line L22 (16.0142, 67.2892) -> (16.2771, 66.1214)
    point P24 (15.1397, 64.9423)
    line L23 (15.1397, 64.9423) -> (16.2771, 66.1214)
    line L24 (16.8052, 63.7761) -> (15.1397, 64.9423)
    distance L1 L2 = 1
    distance L3 L4 = 1
    parallelism: L1 E1, L3 E6, L6 L5, L8 L7
    coincidence: P1 E2, P2 E3, P3 E4, P4 E5, P5 E7, P6 E8, P7 E9, P8 E10, L1 P9, L2 P10, L4 L9, L3 P11, L2 L10, L3 L11, L1 L12
    symmetry: P3 P13 V, P1 P14 V, L8 L13 V, P12 P15 V, L1 L14 V, P5 P16 V, L3 L15 V, P7 P17 V, L5 L16 V, P9 P18 V, L4 L17 V, P2 P19 V, L12 L18 V, P4 P20 V, L6 L19 V, P10 P21 V, L10 L20 V, P8 P22 V, L9 L21 V, P6 P23 V, L7 L22 V, P11 P24 V, L11 L23 V, L2 L24 V
  Pocket25: profile Sketch47, direction (0, 0.9743, -0.2252), length 0.5
  Sketch48 on face of CloseSurface4, origin (0, -33.1899, 7.6699), H (1, 0, 0), V (0, 0.2252, 0.9743)
    line L1 (-16.0142, 67.2892) -> (-11.788, 67.2892)
    point P1 (-16.0142, 67.2892)
    point P2 (-11.788, 67.2892)
    reference projected point E1 (-16.0142, 67.2892) from vertex [face of Pocket25 from Sketch47.L9 | face of Pocket13 from Sketch35.L11 | face of CloseSurface4]
    reference projected line E2 (-11.7455, 67.3189) -> (-14.3104, 65.523) from edge [face of CloseSurface4 | face of Pocket25 from Sketch47.L10]
    line L2 (-16.1134, 68.2892) -> (-11.359, 68.2892)
    point P3 (-16.1134, 68.2892)
    point P4 (-11.359, 68.2892)
    line L3 (-16.0142, 67.2892) -> (-16.1134, 68.2892)
    line L4 (-11.788, 67.2892) -> (-11.359, 67.2892)
    point P5 (-11.359, 67.2892)
    line L5 (-11.359, 67.2892) -> (-11.359, 68.2892)
    point P6 (11.788, 67.2892)
    point P7 (16.0142, 67.2892)
    line L6 (16.0142, 67.2892) -> (11.788, 67.2892)
    point P8 (16.1134, 68.2892)
    line L7 (16.0142, 67.2892) -> (16.1134, 68.2892)
    point P9 (11.359, 68.2892)
    line L8 (16.1134, 68.2892) -> (11.359, 68.2892)
    point P10 (11.359, 67.2892)
    line L9 (11.359, 67.2892) -> (11.359, 68.2892)
    line L10 (11.788, 67.2892) -> (11.359, 67.2892)
    distance L1 L2 = 1
    horizontal: L1 H, L2 H, L4 H
    coincidence: P1 E1, P2 E2
    vertical: L5 V
    symmetry: P2 P6 V, P1 P7 V, L1 L6 V, P3 P8 V, L3 L7 V, P4 P9 V, L2 L8 V, P5 P10 V, L5 L9 V, L4 L10 V
  Pocket26: profile Sketch48, direction (0, 0.9743, -0.2252), length 0.5
  CircPattern27: of Pocket25, instances 4, angular step 90, axis from edge [ZX plane of AxisSystem1 | YZ plane of AxisSystem1]
  CircPattern28: of Pocket26, instances 4, angular step 90, axis from edge [ZX plane of AxisSystem1 | YZ plane of AxisSystem1]
  Sketch49 on face of CloseSurface4, origin (0, -33.1899, 7.6699), H (1, 0, 0), V (0, 0.2252, 0.9743)
    line L1 (-15.789, 68.2892) -> (-13.2745, 70.0498)
    point P1 (-15.789, 68.2892)
    point P2 (-10.9896, 71.6498)
    reference projected line E1 (-11.7455, 67.3189) -> (-14.3104, 65.523) from edge [face of CloseSurface4 | face of Pocket25 from Sketch47.L10]
    reference projected point E2 (-15.789, 68.2892) from vertex [face of Pocket26 from Sketch48.L2 | face of Pocket13 from Sketch35.L11 | face of CloseSurface4]
    reference projected line E3 (-8.6194, 85.2285) -> (-15.0151, 48.5877) from edge [face of CloseSurface4 | face of Pocket13 from Sketch35.L10]
    line L2 (-11.5762, 68.2892) -> (-13.2745, 70.0498)
    point P3 (-11.5762, 68.2892)
    point P4 (-14.9917, 71.8301)
    reference projected line E4 (-14.3104, 65.523) -> (-16.0142, 67.2892) from edge [face of CloseSurface4 | face of Pocket25 from Sketch47.L9]
    reference projected line E5 (-8.6194, 85.2285) -> (-15.0151, 48.5877) from edge [face of CloseSurface4 | face of Pocket13 from Sketch35.L10]
    reference projected line E6 (-11.5762, 68.2892) -> (-15.789, 68.2892) from edge [face of CloseSurface4 | face of Pocket26 from Sketch48.L2]
    line L3 (-15.4627, 69.7384) -> (-13.9774, 70.7785)
    point P5 (-15.4627, 69.7384)
    point P6 (-10.7468, 73.0405)
    reference projected line E7 (-20.225, 48.5877) -> (-11.975, 85.2285) from edge [face of CloseSurface4 | face of Pocket13 from Sketch35.L11]
    reference projected line E8 (-8.6194, 85.2285) -> (-15.0151, 48.5877) from edge [face of CloseSurface4 | face of Pocket13 from Sketch35.L10]
    reference projected line E9 (-20.225, 48.5877) -> (-11.975, 85.2285) from edge [face of CloseSurface4 | face of Pocket13 from Sketch35.L11]
    line L4 (-11.3633, 69.5089) -> (-12.4452, 70.6305)
    point P7 (-11.3633, 69.5089)
    point P8 (-14.7288, 72.9979)
    reference projected line E10 (-8.6194, 85.2285) -> (-15.0151, 48.5877) from edge [face of CloseSurface4 | face of Pocket13 from Sketch35.L10]
    reference projected line E11 (-20.225, 48.5877) -> (-11.975, 85.2285) from edge [face of CloseSurface4 | face of Pocket13 from Sketch35.L11]
    line L5 (-11.5762, 68.2892) -> (-11.3633, 69.5089)
    line L6 (-10.9896, 71.6498) -> (-10.7468, 73.0405)
    line L7 (-14.7288, 72.9979) -> (-14.9917, 71.8301)
    line L8 (-15.4627, 69.7384) -> (-15.789, 68.2892)
    point P9 (-13.2745, 70.0498)
    line L9 (-12.4452, 70.6305) -> (-10.9896, 71.6498)
    point P10 (-12.4452, 70.6305)
    line L10 (-13.1481, 71.3592) -> (-14.7288, 72.9979)
    point P11 (-13.1481, 71.3592)
    point P12 (-13.9774, 70.7785)
    line L11 (-13.1481, 71.3592) -> (-10.7468, 73.0405)
    line L12 (-13.9774, 70.7785) -> (-14.9917, 71.8301)
    point P13 (15.789, 68.2892)
    point P14 (15.4627, 69.7384)
    line L13 (15.4627, 69.7384) -> (15.789, 68.2892)
    point P15 (13.2745, 70.0498)
    line L14 (15.789, 68.2892) -> (13.2745, 70.0498)
    point P16 (11.5762, 68.2892)
    line L15 (11.5762, 68.2892) -> (13.2745, 70.0498)
    point P17 (11.3633, 69.5089)
    line L16 (11.5762, 68.2892) -> (11.3633, 69.5089)
    point P18 (12.4452, 70.6305)
    line L17 (11.3633, 69.5089) -> (12.4452, 70.6305)
    point P19 (10.9896, 71.6498)
    line L18 (12.4452, 70.6305) -> (10.9896, 71.6498)
    point P20 (10.7468, 73.0405)
    line L19 (10.9896, 71.6498) -> (10.7468, 73.0405)
    point P21 (13.1481, 71.3592)
    line L20 (13.1481, 71.3592) -> (10.7468, 73.0405)
    point P22 (14.7288, 72.9979)
    line L21 (13.1481, 71.3592) -> (14.7288, 72.9979)
    point P23 (14.9917, 71.8301)
    line L22 (14.7288, 72.9979) -> (14.9917, 71.8301)
    point P24 (13.9774, 70.7785)
    line L23 (13.9774, 70.7785) -> (14.9917, 71.8301)
    line L24 (15.4627, 69.7384) -> (13.9774, 70.7785)
    distance L1 L3 = 1
    distance L2 L4 = 1
    parallelism: L1 E1, L2 E4, L6 L5, L8 L7
    coincidence: P1 E2, P2 E3, P3 E5, P3 E6, P5 E7, P6 E8, P4 E9, P7 E10, P8 E11, L1 L9, L3 P11, L4 L10, L2 P12, L3 L11, L2 L12
    symmetry: P1 P13 V, P5 P14 V, L8 L13 V, P9 P15 V, L1 L14 V, P3 P16 V, L2 L15 V, P7 P17 V, L5 L16 V, P10 P18 V, L4 L17 V, P2 P19 V, L9 L18 V, P6 P20 V, L6 L19 V, P11 P21 V, L11 L20 V, P8 P22 V, L10 L21 V, P4 P23 V, L7 L22 V, P12 P24 V, L12 L23 V, L3 L24 V
  Pocket27: profile Sketch49, direction (0, 0.9743, -0.2252), length 0.5
  Sketch50 on face of CloseSurface4, origin (0, -33.1899, 7.6699), H (1, 0, 0), V (0, 0.2252, 0.9743)
    line L1 (-14.7288, 72.9979) -> (-10.2288, 72.9979)
    point P1 (-14.7288, 72.9979)
    point P2 (-10.2288, 72.9979)
    reference projected point E1 (-14.7288, 72.9979) from vertex [face of Pocket27 from Sketch49.L10 | face of Pocket13 from Sketch35.L11 | face of CloseSurface4]
    line L2 (-14.7288, 73.9979) -> (-10.2288, 73.9979)
    point P3 (-14.7288, 73.9979)
    point P4 (-10.2288, 73.9979)
    line L3 (-10.2288, 72.9979) -> (-10.2288, 73.9979)
    line L4 (-14.7288, 73.9979) -> (-14.7288, 72.9979)
    point P5 (10.2288, 72.9979)
    point P6 (14.7288, 72.9979)
    line L5 (14.7288, 72.9979) -> (10.2288, 72.9979)
    point P7 (14.7288, 73.9979)
    line L6 (14.7288, 73.9979) -> (14.7288, 72.9979)
    point P8 (10.2288, 73.9979)
    line L7 (14.7288, 73.9979) -> (10.2288, 73.9979)
    line L8 (10.2288, 72.9979) -> (10.2288, 73.9979)
    distance L1 L2 = 1
    horizontal: L1 H, L2 H
    coincidence: P1 E1
    vertical: L3 V, L4 V
    symmetry: P2 P5 V, P1 P6 V, L1 L5 V, P3 P7 V, L4 L6 V, P4 P8 V, L2 L7 V, L3 L8 V
  Pocket28: profile Sketch50, direction (0, 0.9743, -0.2252), length 0.5
  CircPattern29: of Pocket27, instances 4, angular step 90, axis from edge [ZX plane of AxisSystem1 | YZ plane of AxisSystem1]
  CircPattern30: of Pocket28, instances 4, angular step 90, axis from edge [ZX plane of AxisSystem1 | YZ plane of AxisSystem1]
  Sketch51 on face of CloseSurface4, origin (0, -33.1899, 7.6699), H (1, 0, 0), V (0, 0.2252, 0.9743)
    line L1 (-14.5036, 73.9979) -> (-12.1616, 75.6378)
    point P1 (-14.5036, 73.9979)
    point P2 (-10.0333, 77.128)
    reference projected line E1 (-10.7468, 73.0405) -> (-13.1481, 71.3592) from edge [face of CloseSurface4 | face of Pocket27 from Sketch49.L11]
    reference projected point E2 (-14.5036, 73.9979) from vertex [face of Pocket28 from Sketch50.L2 | face of Pocket13 from Sketch35.L11 | face of CloseSurface4]
    reference projected line E3 (-8.6194, 85.2285) -> (-15.0151, 48.5877) from edge [face of CloseSurface4 | face of Pocket13 from Sketch35.L10]
    line L2 (-14.1773, 75.4471) -> (-12.8644, 76.3664)
    point P3 (-14.1773, 75.4471)
    point P4 (-9.7906, 78.5188)
    reference projected line E4 (-20.225, 48.5877) -> (-11.975, 85.2285) from edge [face of CloseSurface4 | face of Pocket13 from Sketch35.L11]
    reference projected line E5 (-8.6194, 85.2285) -> (-15.0151, 48.5877) from edge [face of CloseSurface4 | face of Pocket13 from Sketch35.L10]
    line L3 (-10.5797, 73.9979) -> (-12.1616, 75.6378)
    point P5 (-10.5797, 73.9979)
    point P6 (-13.7611, 77.296)
    reference projected point E6 (-10.5797, 73.9979) from vertex [face of Pocket28 from Sketch50.L2 | face of Pocket13 from Sketch35.L10 | face of CloseSurface4]
    reference projected line E7 (-20.225, 48.5877) -> (-11.975, 85.2285) from edge [face of CloseSurface4 | face of Pocket13 from Sketch35.L11]
    reference projected line E8 (-13.1481, 71.3592) -> (-14.7288, 72.9979) from edge [face of CloseSurface4 | face of Pocket27 from Sketch49.L10]
    line L4 (-10.3668, 75.2176) -> (-11.3323, 76.2185)
    point P7 (-10.3668, 75.2176)
    point P8 (-13.4981, 78.4638)
    reference projected line E9 (-8.6194, 85.2285) -> (-15.0151, 48.5877) from edge [face of CloseSurface4 | face of Pocket13 from Sketch35.L10]
    reference projected line E10 (-20.225, 48.5877) -> (-11.975, 85.2285) from edge [face of CloseSurface4 | face of Pocket13 from Sketch35.L11]
    line L5 (-10.5797, 73.9979) -> (-10.3668, 75.2176)
    line L6 (-10.0333, 77.128) -> (-9.7906, 78.5188)
    line L7 (-13.4981, 78.4638) -> (-13.7611, 77.296)
    line L8 (-14.1773, 75.4471) -> (-14.5036, 73.9979)
    point P9 (-12.1616, 75.6378)
    line L9 (-11.3323, 76.2185) -> (-10.0333, 77.128)
    point P10 (-11.3323, 76.2185)
    line L10 (-12.0351, 76.9471) -> (-13.4981, 78.4638)
    point P11 (-12.0351, 76.9471)
    point P12 (-12.8644, 76.3664)
    line L11 (-12.0351, 76.9471) -> (-9.7906, 78.5188)
    line L12 (-12.8644, 76.3664) -> (-13.7611, 77.296)
    point P13 (14.5036, 73.9979)
    point P14 (14.1773, 75.4471)
    line L13 (14.1773, 75.4471) -> (14.5036, 73.9979)
    point P15 (12.1616, 75.6378)
    line L14 (14.5036, 73.9979) -> (12.1616, 75.6378)
    point P16 (10.5797, 73.9979)
    line L15 (10.5797, 73.9979) -> (12.1616, 75.6378)
    point P17 (10.3668, 75.2176)
    line L16 (10.5797, 73.9979) -> (10.3668, 75.2176)
    point P18 (11.3323, 76.2185)
    line L17 (10.3668, 75.2176) -> (11.3323, 76.2185)
    point P19 (10.0333, 77.128)
    line L18 (11.3323, 76.2185) -> (10.0333, 77.128)
    point P20 (9.7906, 78.5188)
    line L19 (10.0333, 77.128) -> (9.7906, 78.5188)
    point P21 (12.0351, 76.9471)
    line L20 (12.0351, 76.9471) -> (9.7906, 78.5188)
    point P22 (13.4981, 78.4638)
    line L21 (12.0351, 76.9471) -> (13.4981, 78.4638)
    point P23 (13.7611, 77.296)
    line L22 (13.4981, 78.4638) -> (13.7611, 77.296)
    point P24 (12.8644, 76.3664)
    line L23 (12.8644, 76.3664) -> (13.7611, 77.296)
    line L24 (14.1773, 75.4471) -> (12.8644, 76.3664)
    distance L2 L1 = 1
    distance L3 L4 = 1
    parallelism: L1 E1, L3 E8, L6 L5, L8 L7
    coincidence: P1 E2, P2 E3, P3 E4, P4 E5, P5 E6, P6 E7, P7 E9, P8 E10, L1 L9, L2 P11, L4 L10, L3 P12, L2 L11, L3 L12
    symmetry: P1 P13 V, P3 P14 V, L8 L13 V, P9 P15 V, L1 L14 V, P5 P16 V, L3 L15 V, P7 P17 V, L5 L16 V, P10 P18 V, L4 L17 V, P2 P19 V, L9 L18 V, P4 P20 V, L6 L19 V, P11 P21 V, L11 L20 V, P8 P22 V, L10 L21 V, P6 P23 V, L7 L22 V, P12 P24 V, L12 L23 V, L2 L24 V
  Pocket29: profile Sketch51, direction (0, 0.9743, -0.2252), length 0.5
  Sketch52 on face of CloseSurface4, origin (0, -33.1899, 7.6699), H (1, 0, 0), V (0, 0.2252, 0.9743)
    line L1 (-13.4981, 78.4638) -> (-9.4981, 78.4638)
    point P1 (-13.4981, 78.4638)
    point P2 (-9.4981, 78.4638)
    reference projected point E1 (-13.4981, 78.4638) from vertex [face of Pocket29 from Sketch51.L10 | face of Pocket13 from Sketch35.L11 | face of CloseSurface4]
    line L2 (-13.4981, 79.4638) -> (-9.349, 79.4638)
    point P3 (-13.4981, 79.4638)
    point P4 (-9.349, 79.4638)
    line L3 (-9.4981, 78.4638) -> (-9.349, 79.4638)
    line L4 (-13.4981, 79.4638) -> (-13.4981, 78.4638)
    point P5 (9.4981, 78.4638)
    point P6 (13.4981, 78.4638)
    line L5 (13.4981, 78.4638) -> (9.4981, 78.4638)
    point P7 (13.4981, 79.4638)
    line L6 (13.4981, 79.4638) -> (13.4981, 78.4638)
    point P8 (9.349, 79.4638)
    line L7 (13.4981, 79.4638) -> (9.349, 79.4638)
    line L8 (9.4981, 78.4638) -> (9.349, 79.4638)
    distance L2 L1 = 1
    horizontal: L1 H, L2 H
    coincidence: P1 E1
    vertical: L4 V
    symmetry: P2 P5 V, P1 P6 V, L1 L5 V, P3 P7 V, L4 L6 V, P4 P8 V, L2 L7 V, L3 L8 V
  Pocket30: profile Sketch52, direction (0, 0.9743, -0.2252), length 0.5
  CircPattern31: of Pocket29, instances 4, angular step 90, axis from edge [ZX plane of AxisSystem1 | YZ plane of AxisSystem1]
  CircPattern32: of Pocket30, instances 4, angular step 90, axis from edge [ZX plane of AxisSystem1 | YZ plane of AxisSystem1]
